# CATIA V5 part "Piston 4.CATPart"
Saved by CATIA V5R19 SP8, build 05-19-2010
Part number: Piston 4
Bounding box of the stored display mesh (mm): x -300 to 0, y -1400 to 107.535, z 1348.121 to 3749.807
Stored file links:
  C:\Users\ThinkMotion\Desktop\EU_thinkMotion\iao\IAO_MMS_Groupe3\fovide\fovide\Piston 4.CATPart
  C:\Users\ThinkMotion\Desktop\EU_thinkMotion\iao\IAO_MMS_Groupe3\fovide\fovide\fovide.CATProduct
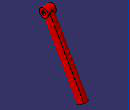
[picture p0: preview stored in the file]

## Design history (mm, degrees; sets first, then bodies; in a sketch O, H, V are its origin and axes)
External parameters (linked from other documents)
  `External.Rayon bielle` = 75 mm
  `External.Diamètre bielle` = 150 mm
Set1
  Plane1: linked copy from another document
  Line1: linked copy from another document
  Point1 "Point.E": linked copy from another document
  Line2: linked copy from another document
Body1 (main body)
  Sketch1 on Plane1, origin (-150, 0, 0), H (0, 1, 0), V (0, 0, 1)
    circle A1 centre (-1250, 3600) radius 150
    point P1 (-1250, 3600)
    reference projected point E1 (-1250, 3600) from Point1
    radius A1 = 150 {= `External.Diamètre bielle`}
    coincidence: P1 E1
  Pad1: profile Sketch1, direction (1, 0, 0), length 150 {= `External.Diamètre bielle`}, mirrored extent
  Sketch2 on end face of Pad1, origin (0, -1250, 3600), H (0, 1, 0), V (0, 0, 1)
    point P1 (0, 0)
    intersected point E1 (0, 0) from Line2
    coincidence: E1 P1
  Hole1: placed by Sketch2, at (0, -1250, 3600) direction (-1, 0, 0), diameter 150 {= `External.Diamètre bielle`}, through (limit type 6)
  Sketch3 on Plane1, origin (-150, 0, 0), H (0, 1, 0), V (0, 0, 1)
    point P1 (-1250, 3600)
    line L1 (-1250, 3600) -> (-1119.3038, 3673.6105)
    line L2 (-1119.3038, 3673.6105) -> (107.5378, 1495.3406)
    reference projected point E1 (-1250, 3600) from Point1
    line L3 (-1250, 3600) -> (-1012.8055, 3178.8587)
    point P4 (-1250, 3600)
    reference projected point E2 (-1250, 3600) from Point1
    line L4 (-1012.8055, 3178.8587) -> (-947.4574, 3215.664)
    line L5 (-947.4574, 3215.664) -> (42.1897, 1458.5354)
    point P7 (42.1897, 1458.5354)
    line L6 (42.1897, 1458.5354) -> (107.5378, 1495.3406)
    point P8 (42.1897, 1458.5354)
    reference projected line E3 (-1250, 3600) -> (1200, -750) from Line1
    length L2 = 2500
    length L1 = 150 {= `External.Rayon bielle` *2}
    length L4 = 75 {= `External.Rayon bielle`}
    coincidence: P1 E1, P4 E2, P8 L5, P1 P4, P7 P8
    parallelism: L3 L2, L4 L1, L5 L2, L3 E3, L1 L6
    perpendicularity: L6 L2, L1 L3, L3 L4, L4 L5
  Shaft1: profile Sketch3, axis Sketch3.L3, angle 360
